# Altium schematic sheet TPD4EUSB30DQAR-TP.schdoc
size 127 x 101 mm
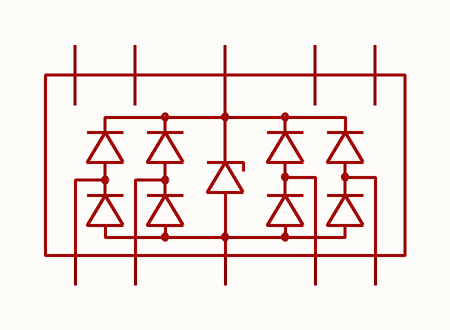
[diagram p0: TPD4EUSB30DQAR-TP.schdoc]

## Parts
D?  tpd4eusb30dqar-tp  [DFN2510-10_L2.5-W1.0-P0.50-BL]  (value not drawn)

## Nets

Not connected (* = marked no-connect by the designer): D? 1(D1+) 2(D1-) 3(GND) 4(D2+) 5(D2-) 6(NC) 7(NC) 8(GND) 9(NC) 10(NC)

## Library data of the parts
D? = tpd4eusb30dqar-tp: 极性:单向;反向截止电压(Vrwm):5V;钳位电压:25V;峰值脉冲电流(Ipp):4A@8/20us;峰值脉冲功率(Ppp):100W@8/20us;击穿电压:8V;; Manufacturer: TECH PUBLIC(台舟); AddInBom: yes; ModelId: 55525fa8fc914f7c8ffcb10749ea5f73; ModelName: DFN-10_L2.5-W1.0-H0.5-P0.50; ModelTransform: 40.1574,98.425,0,90,0,0,0,0,0; Polarity: 单向; Reverse Stand-Off Voltage (Vrwm): 5V; Clamping Voltage: 25V; Voltage - Breakdown: 8V; Reverse Leakage Current (Ir): 400nA; Number of Channels: 四路; level of protection: IEC 61000-4-4；IEC 61000-4-5；IEC 61000-4-2; Junction Capacitance: 0.3pF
